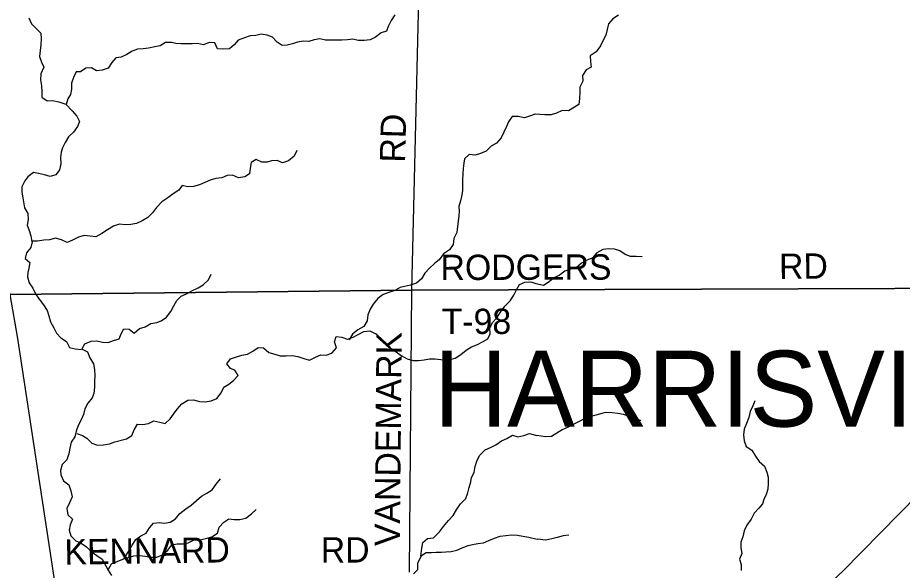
# Model space of a CAD drawing. Extents: x 1985906 to 2277390, y 930619 to 1324581.
# Drawn here: x 2100293 to 2110785, y 1112733 to 1119287 of the extents above; entities that cross this region are included whole.
import ezdxf

# ---------------------------------------------------------------- set-up
doc = ezdxf.new("R2010")
doc.units = 0
for name, color, linetype in [('GM_X_County_Road', 7, 'Continuous'), ('GM_X_County_Road_Text', 7, 'Continuous'), ('GM_X_Minor_River', 7, 'Continuous'), ('GM_X_State_Route', 7, 'Continuous'), ('GM_X_Township', 7, 'Continuous'), ('GM_X_Township_Road', 7, 'Continuous'), ('GM_X_Township_Road_Text', 7, 'Continuous'), ('GM_X_Township_Text', 7, 'Continuous'), ('GM_X_US_Route', 7, 'Continuous')]:
    doc.layers.add(name, color=color, linetype=linetype)

msp = doc.modelspace()

# ---------------------------------------------------------------- linework, layer by layer
at = {"layer": 'GM_X_County_Road'}
for points in [[(2104969, 1116054), (2105090, 1121154)], [(2104940, 1112710), (2104969, 1116054)]]:
    msp.add_lwpolyline(points, dxfattribs=at)
at = {"layer": 'GM_X_Minor_River'}
for points in [[(2100425, 1119287), (2100458, 1119215), (2100513, 1119158), (2100567, 1119104), (2100570, 1119036), (2100569, 1118965), (2100559, 1118897), (2100552, 1118825), (2100576, 1118761), (2100603, 1118699), (2100566, 1118620), (2100564, 1118548), (2100575, 1118480), (2100577, 1118408), (2100580, 1118343), (2100641, 1118302), (2100707, 1118306), (2100779, 1118289), (2100865, 1118261)], [(2104765, 1119321), (2104723, 1119252), (2104688, 1119182), (2104666, 1119125), (2104602, 1119109), (2104538, 1119054), (2104472, 1119026), (2104402, 1119017), (2104330, 1119018), (2104269, 1119034), (2104205, 1119025), (2104139, 1119021), (2104089, 1119021), (2104010, 1119022), (2103944, 1119019), (2103876, 1119035), (2103808, 1119024), (2103746, 1119004), (2103681, 1119007), (2103613, 1118995), (2103551, 1118978), (2103487, 1118962), (2103431, 1118955), (2103370, 1118997), (2103314, 1119057), (2103253, 1119078), (2103181, 1119092), (2103117, 1119075), (2103049, 1119071), (2102983, 1119048), (2102909, 1119020), (2102861, 1118965), (2102805, 1118916), (2102737, 1118912), (2102663, 1118919), (2102630, 1118987), (2102564, 1118991), (2102495, 1118966), (2102427, 1118980), (2102361, 1118977), (2102297, 1118977), (2102228, 1118978), (2102168, 1118982), (2102118, 1118993), (2102046, 1118991), (2101982, 1118952), (2101918, 1118942), (2101845, 1118925), (2101781, 1118919), (2101715, 1118914), (2101651, 1118889), (2101589, 1118851), (2101521, 1118818), (2101455, 1118812), (2101409, 1118757), (2101364, 1118687), (2101296, 1118666), (2101226, 1118657), (2101167, 1118691), (2101101, 1118689), (2101037, 1118644), (2100987, 1118646), (2100955, 1118577)], [(2107417, 1119317), (2107353, 1119275), (2107301, 1119213), (2107283, 1119146), (2107267, 1119078), (2107235, 1119012), (2107207, 1118952), (2107153, 1118883), (2107083, 1118833), (2107087, 1118765), (2107094, 1118699), (2107035, 1118669), (2106991, 1118600), (2106996, 1118534), (2106960, 1118462), (2106960, 1118398), (2106958, 1118329), (2106947, 1118259), (2106826, 1118183), (2106752, 1118186), (2106684, 1118154), (2106620, 1118136), (2106547, 1118134), (2106427, 1118141)], [(2100955, 1118577), (2100932, 1118509), (2100932, 1118440), (2100917, 1118376), (2100889, 1118326), (2100868, 1118257)], [(2100862, 1118261), (2100939, 1118182), (2100995, 1118120), (2101024, 1118056), (2101003, 1117996), (2100955, 1117929), (2100897, 1117872), (2100856, 1117808), (2100826, 1117743), (2100809, 1117693), (2100801, 1117629), (2100804, 1117554), (2100788, 1117482), (2100745, 1117422), (2100677, 1117405), (2100610, 1117423), (2100540, 1117440), (2100479, 1117452), (2100412, 1117401), (2100378, 1117351), (2100340, 1117282), (2100341, 1117218), (2100354, 1117152), (2100362, 1117102), (2100373, 1117031), (2100413, 1116966), (2100418, 1116893), (2100403, 1116825), (2100425, 1116773), (2100448, 1116701), (2100461, 1116629)], [(2106431, 1118143), (2106375, 1118123), (2106303, 1118100), (2106230, 1118114), (2106156, 1118113), (2106115, 1118051), (2106091, 1117998), (2106028, 1117861), (2105972, 1117799), (2105908, 1117762), (2105849, 1117702), (2105783, 1117675), (2105717, 1117656), (2105648, 1117666), (2105593, 1117611), (2105585, 1117561), (2105577, 1117497), (2105574, 1117433), (2105567, 1117366), (2105568, 1117234), (2105556, 1117166), (2105543, 1117115), (2105527, 1117047), (2105528, 1116997), (2105524, 1116933), (2105519, 1116878), (2105500, 1116738), (2105466, 1116669), (2105457, 1116595), (2105415, 1116532), (2105345, 1116486), (2105290, 1116415), (2105238, 1116372), (2105176, 1116318), (2105121, 1116255), (2105083, 1116189), (2105021, 1116140), (2104951, 1116115), (2104881, 1116097), (2104829, 1116086), (2104767, 1116052), (2104693, 1116027), (2104629, 1116003), (2104565, 1115956), (2104508, 1115891), (2104474, 1115829), (2104447, 1115764), (2104437, 1115692), (2104400, 1115626), (2104326, 1115583), (2104262, 1115532), (2104226, 1115466)], [(2103602, 1117712), (2103571, 1117644), (2103505, 1117589), (2103433, 1117567), (2103369, 1117592), (2103302, 1117590), (2103252, 1117573), (2103188, 1117575), (2103122, 1117606), (2103062, 1117568), (2103050, 1117501), (2103043, 1117433), (2102985, 1117399), (2102911, 1117386), (2102842, 1117420), (2102778, 1117415), (2102714, 1117389), (2102642, 1117380), (2102574, 1117359), (2102514, 1117333), (2102448, 1117304), (2102378, 1117286), (2102310, 1117281), (2102243, 1117297), (2102202, 1117242), (2102136, 1117199), (2102072, 1117149), (2102004, 1117104), (2101938, 1117037), (2101891, 1116971), (2101837, 1116918), (2101769, 1116876), (2101701, 1116847), (2101633, 1116836), (2101569, 1116832), (2101499, 1116839), (2101428, 1116813), (2101357, 1116770), (2101289, 1116727), (2101219, 1116689), (2101151, 1116694), (2101080, 1116702), (2101012, 1116683), (2100944, 1116647), (2100880, 1116622), (2100814, 1116654), (2100741, 1116671), (2100671, 1116652), (2100601, 1116650), (2100529, 1116635), (2100461, 1116637)], [(2100463, 1116627), (2100449, 1116562), (2100398, 1116498), (2100380, 1116432), (2100435, 1116384), (2100423, 1116315), (2100414, 1116265), (2100410, 1116215), (2100427, 1116143), (2100473, 1116077), (2100504, 1116011), (2100549, 1115947), (2100600, 1115881), (2100642, 1115815), (2100661, 1115749), (2100682, 1115679), (2100720, 1115607), (2100751, 1115547), (2100804, 1115490), (2100870, 1115448), (2100907, 1115376), (2100975, 1115361), (2101049, 1115353)], [(2107701, 1116451), (2107628, 1116454), (2107560, 1116456), (2107498, 1116480), (2107433, 1116520), (2107371, 1116540), (2107303, 1116546), (2107234, 1116537), (2107162, 1116499), (2107106, 1116435), (2107042, 1116413), (2106980, 1116374), (2106918, 1116322), (2106849, 1116304), (2106781, 1116282), (2106717, 1116231), (2106653, 1116203), (2106595, 1116155), (2106531, 1116110), (2106439, 1116131)], [(2101054, 1115356), (2101090, 1115420), (2101164, 1115449), (2101232, 1115454), (2101300, 1115438), (2101365, 1115435), (2101429, 1115457), (2101495, 1115478), (2101520, 1115538), (2101550, 1115597), (2101616, 1115593), (2101673, 1115546), (2101737, 1115600), (2101805, 1115621), (2101871, 1115658), (2101943, 1115672), (2101993, 1115691), (2102059, 1115735), (2102111, 1115802), (2102144, 1115871), (2102182, 1115931), (2102232, 1115986), (2102294, 1116012), (2102366, 1116053), (2102432, 1116084), (2102494, 1116118), (2102556, 1116179), (2102589, 1116246)], [(2100994, 1114355), (2101060, 1114333), (2101111, 1114301), (2101173, 1114242), (2101238, 1114218), (2101310, 1114221), (2101382, 1114233), (2101446, 1114256), (2101583, 1114291), (2101647, 1114332), (2101676, 1114398), (2101712, 1114465), (2101776, 1114461), (2101846, 1114474), (2101908, 1114506), (2101977, 1114491), (2102041, 1114475), (2102101, 1114528), (2102139, 1114583), (2102184, 1114645), (2102238, 1114706), (2102312, 1114749), (2102378, 1114755), (2102449, 1114734), (2102517, 1114732), (2102587, 1114743), (2102655, 1114771), (2102707, 1114838), (2102739, 1114903), (2102797, 1114939), (2102852, 1114982), (2102906, 1115043), (2102868, 1115105), (2102815, 1115126), (2102773, 1115180), (2102818, 1115241), (2102886, 1115263), (2102952, 1115284), (2103019, 1115297), (2103081, 1115333), (2103143, 1115376), (2103207, 1115370), (2103270, 1115317), (2103342, 1115295), (2103406, 1115275), (2103477, 1115278), (2103549, 1115281), (2103617, 1115269), (2103686, 1115245), (2103754, 1115226), (2103824, 1115261), (2103888, 1115287), (2103957, 1115286), (2104023, 1115312), (2104074, 1115373), (2104052, 1115443), (2104069, 1115506), (2104138, 1115496), (2104204, 1115476), (2104270, 1115499), (2104332, 1115530), (2104398, 1115564), (2104470, 1115571), (2104539, 1115539), (2104592, 1115481), (2104656, 1115422), (2104717, 1115366), (2104780, 1115324), (2104842, 1115280), (2104913, 1115241), (2104979, 1115223), (2105048, 1115220), (2105114, 1115230), (2105178, 1115239), (2105242, 1115241), (2105311, 1115232), (2105383, 1115230), (2105433, 1115235), (2105483, 1115249), (2105549, 1115294), (2105613, 1115345), (2105677, 1115383), (2105745, 1115412), (2105807, 1115443), (2105869, 1115479), (2105895, 1115538), (2105894, 1115604), (2105926, 1115670), (2105977, 1115729), (2106021, 1115794), (2106069, 1115866), (2106135, 1115927), (2106178, 1115994), (2106208, 1116060), (2106245, 1116121), (2106309, 1116150), (2106380, 1116154), (2106440, 1116133)], [(2101056, 1115356), (2101119, 1115324), (2101149, 1115254), (2101190, 1115182), (2101205, 1115114), (2101209, 1115044), (2101204, 1114975), (2101204, 1114903), (2101195, 1114831), (2101175, 1114780), (2101125, 1114715), (2101088, 1114649), (2101074, 1114582), (2101045, 1114516), (2101011, 1114449), (2100986, 1114383), (2100972, 1114314), (2100926, 1114252), (2100913, 1114183), (2100901, 1114113), (2100874, 1114044), (2100820, 1113988), (2100800, 1113917), (2100803, 1113867), (2100834, 1113795), (2100900, 1113747), (2100923, 1113675), (2100940, 1113603), (2100908, 1113532), (2100874, 1113464), (2100889, 1113391), (2100942, 1113338), (2100916, 1113273), (2100903, 1113209), (2100923, 1113143), (2100982, 1113083), (2101046, 1113053), (2101109, 1113011), (2101168, 1112952), (2101230, 1112908), (2101293, 1112866), (2101366, 1112734), (2101405, 1112670)], [(2109035, 1114744), (2109011, 1114683), (2108979, 1114615), (2108966, 1114547), (2108936, 1114475), (2108908, 1114406), (2108900, 1114338), (2108908, 1114270), (2108933, 1114202), (2109001, 1114158), (2109042, 1114086), (2109088, 1114022), (2109149, 1113966), (2109177, 1113898), (2109193, 1113838), (2109196, 1113764), (2109190, 1113697), (2109172, 1113633), (2109144, 1113571), (2109126, 1113521), (2109084, 1113470), (2109028, 1113412), (2108992, 1113340), (2108942, 1113270), (2108910, 1113199), (2108895, 1113129), (2108871, 1113065), (2108871, 1112999), (2108883, 1112934), (2108855, 1112866), (2108872, 1112800), (2108874, 1112730)], [(2107688, 1114505), (2107620, 1114533), (2107551, 1114557), (2107477, 1114579), (2107410, 1114593), (2107342, 1114601), (2107270, 1114603), (2107220, 1114592), (2107149, 1114574), (2107089, 1114558), (2107019, 1114532), (2106953, 1114497), (2106889, 1114465), (2106822, 1114429), (2106752, 1114399), (2106688, 1114358), (2106626, 1114318), (2106554, 1114314), (2106449, 1114332)], [(2105073, 1112900), (2105088, 1112996), (2105099, 1113062), (2105153, 1113109), (2105225, 1113119), (2105297, 1113190), (2105345, 1113253), (2105404, 1113322), (2105456, 1113384), (2105502, 1113457), (2105543, 1113522), (2105607, 1113586), (2105633, 1113651), (2105646, 1113715), (2105668, 1113782), (2105677, 1113832), (2105705, 1113893), (2105717, 1113965), (2105738, 1114027), (2105772, 1114094), (2105837, 1114161), (2105899, 1114191), (2105964, 1114222), (2106031, 1114269), (2106095, 1114297), (2106161, 1114334), (2106226, 1114316), (2106298, 1114333), (2106365, 1114357), (2106449, 1114332)], [(2101555, 1112874), (2101616, 1112967), (2101651, 1113030), (2101693, 1113098), (2101755, 1113143), (2101817, 1113174), (2101856, 1113236), (2101904, 1113291), (2101972, 1113299), (2102035, 1113290), (2102103, 1113304), (2102163, 1113343), (2102214, 1113408), (2102286, 1113460), (2102352, 1113505), (2102414, 1113560), (2102474, 1113611), (2102536, 1113649), (2102600, 1113688), (2102647, 1113753), (2102699, 1113819)], [(2101364, 1112740), (2101404, 1112809), (2101472, 1112839), (2101540, 1112866), (2101604, 1112885), (2101672, 1112903), (2101736, 1112910), (2101809, 1112900), (2101873, 1112887), (2101943, 1112889), (2102012, 1112918), (2102075, 1112971), (2102119, 1113033), (2102183, 1113048), (2102256, 1113048), (2102316, 1113059), (2102386, 1113093), (2102454, 1113096), (2102526, 1113111), (2102596, 1113129), (2102662, 1113172), (2102682, 1113244), (2102737, 1113305), (2102797, 1113342), (2102860, 1113334), (2102926, 1113335), (2102998, 1113351), (2103064, 1113402), (2103122, 1113455)], [(2104988, 1112691), (2105038, 1112744), (2105039, 1112816), (2105082, 1112909), (2105136, 1112944), (2105201, 1112944), (2105255, 1112949), (2105319, 1112949), (2105371, 1112952), (2105433, 1112954), (2105502, 1112971), (2105564, 1112999), (2105636, 1113026), (2105686, 1113038), (2105752, 1113049), (2105818, 1113057), (2105880, 1113088), (2105948, 1113113), (2106014, 1113139), (2106151, 1113152), (2106221, 1113149), (2106286, 1113139), (2106354, 1113124), (2106456, 1113102)], [(2106831, 1113151), (2106761, 1113143), (2106691, 1113121), (2106627, 1113105), (2106558, 1113091), (2106456, 1113102)], [(2106490, 1113117), (2106491, 1113117)]]:
    msp.add_lwpolyline(points, dxfattribs=at)
at = {"layer": 'GM_X_State_Route'}
msp.add_lwpolyline([(2101667, 1109661), (2101658, 1109676), (2101614, 1109753), (2101104, 1110630), (2101046, 1110743), (2101016, 1110837), (2100743, 1112538), (2100720, 1112677), (2100294, 1115482), (2100205, 1116004), (2100184, 1116081), (2100102, 1116332), (2099623, 1117575), (2099615, 1117635), (2099618, 1117820), (2099619, 1120394), (2099617, 1121238), (2099616, 1121385), (2099622, 1124214), (2099626, 1126250), (2099630, 1128484), (2099636, 1128635)], dxfattribs=at)
at = {"layer": 'GM_X_Township'}
for points in [[(2112984, 1116083), (2104969, 1116054), (2100205, 1116004), (2099440, 1115999), (2095791, 1115975), (2091531, 1115991), (2085329, 1116004), (2085345, 1117751), (2085400, 1120106), (2085480, 1124405), (2085604, 1129650), (2085675, 1134358), (2085729, 1138807), (2085793, 1142829), (2091371, 1142782), (2094059, 1142740), (2099759, 1142765), (2105186, 1142765), (2105809, 1142742), (2113092, 1142777)], [(2091531, 1115991), (2095791, 1115975), (2099440, 1115999), (2100205, 1116004), (2104969, 1116054), (2112984, 1116083)]]:
    msp.add_lwpolyline(points, dxfattribs=at)
at = {"layer": 'GM_X_Township_Road'}
msp.add_lwpolyline([(2104969, 1116054), (2112869, 1116083)], dxfattribs=at)
at = {"layer": 'GM_X_US_Route'}
msp.add_lwpolyline([(2108478, 1111092), (2108484, 1111097), (2108981, 1111605), (2110034, 1112679), (2110078, 1112724), (2112980, 1115675), (2113389, 1116085), (2117701, 1120584), (2119808, 1122792), (2120305, 1123313), (2122862, 1125978), (2123167, 1126295)], dxfattribs=at)

# ---------------------------------------------------------------- texts
at = {"layer": 'GM_X_County_Road_Text'}
for s, rotation, p in [('RD', 88.5194, (2104887, 1117565)), ('VANDEMARK', 89.4715, (2104825, 1113018)), ('KENNARD', 0.8448, (2100849, 1112799)), ('RD', 0, (2103887, 1112825))]:
    msp.add_text(s, height=300, rotation=rotation, dxfattribs=at).set_placement(p)
at = {"layer": 'GM_X_Township_Road_Text'}
for s, rotation, p in [('RODGERS', 0.1472, (2105308, 1116175)), ('RD', 0.4936, (2109324, 1116188)), ('T-98', 0, (2105321, 1115536))]:
    msp.add_text(s, height=300, rotation=rotation, dxfattribs=at).set_placement(p)
at = {"layer": 'GM_X_Township_Text'}
msp.add_text('HARRISVILLE', height=900, rotation=0, dxfattribs=at).set_placement((2105229, 1114437))

doc.saveas('drawing.dxf')
